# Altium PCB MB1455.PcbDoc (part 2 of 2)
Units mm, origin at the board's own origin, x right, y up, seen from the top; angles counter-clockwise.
Board outline 18.54 x 50.29 mm, 4 copper layers (Top Layer, Inner 1, Inner 2, Bottom Layer), stack 1.577 mm thick; 92 components, 84 nets, 350 pads, 195 vias.
Unrouted connection lines stored in the file: 7.
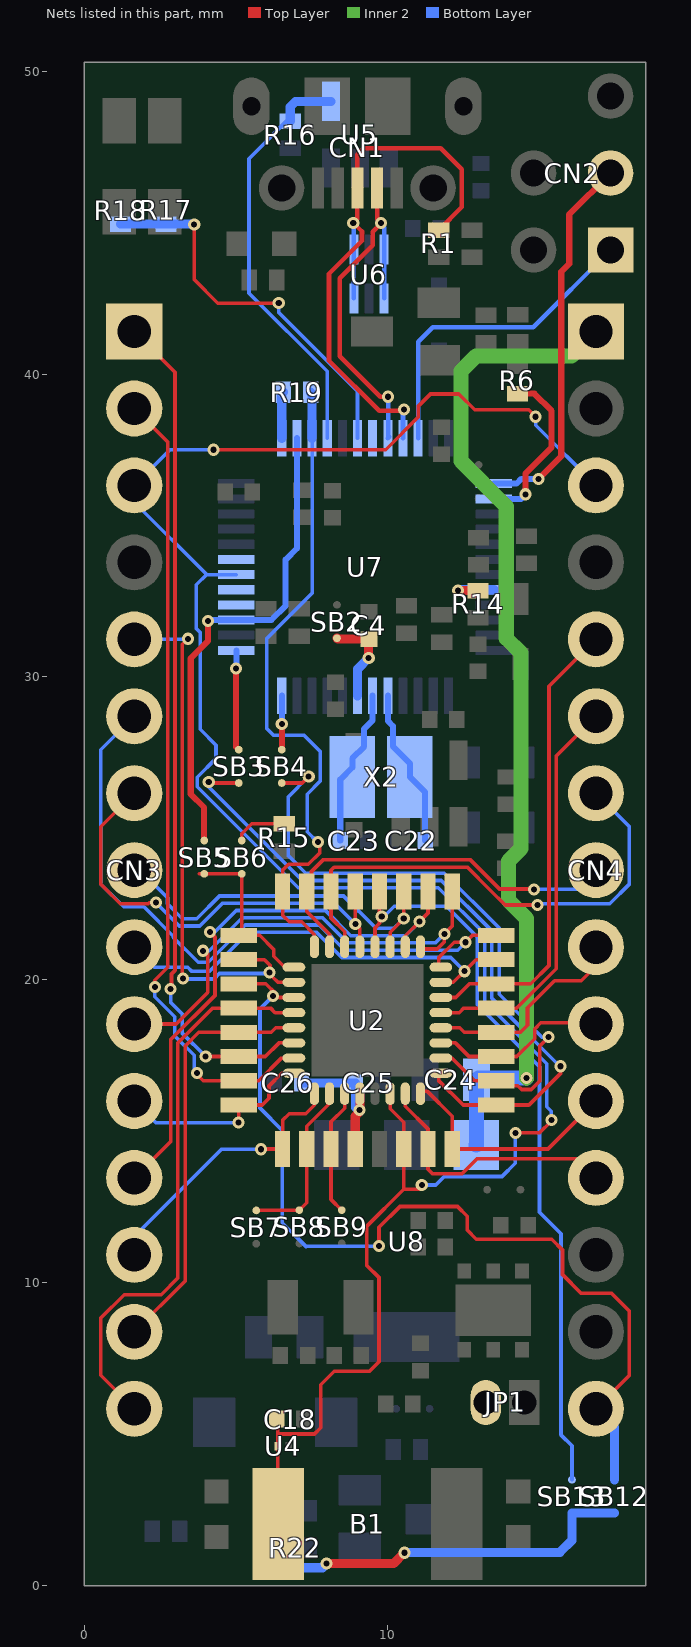
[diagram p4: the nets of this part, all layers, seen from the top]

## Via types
v1: diameter 0.4, hole 0.2, Top Layer to Bottom Layer, 195 vias

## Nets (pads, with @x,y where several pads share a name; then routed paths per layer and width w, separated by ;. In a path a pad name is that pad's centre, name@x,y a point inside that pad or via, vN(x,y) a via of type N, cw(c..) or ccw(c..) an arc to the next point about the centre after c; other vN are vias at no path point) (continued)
NetR14_2: R14.2 U7.44 | length 1.9
  Top Layer w0.3: v1(12.34,32.86) 12.99,32.86 R14.2@13,32.85
  Bottom Layer w0.3: v1(12.34,32.86) 12.36,32.88 U7.44@13.521,32.88
NetR15_2: R15.2 SB6.1 | length 1.8
  Top Layer w0.12: SB6.1@5.2,24.6 5.2,24.82 5.53,25.15 R15.2@6.6,25.15
NetR22_1: R22.1 SB12.2 SB13.2 | length 12.8
  Top Layer w0.3: v1(8,0.729) 10.209,0.729 v1(10.57,1.09)
  Bottom Layer w0.3: R22.1@6.521,1.25 6.521,0.739 6.665,0.595 7.866,0.595 v1(8,0.729) ; v1(10.57,1.09) 10.58,1.1 15.7,1.1 16.1,1.5 SB13.2@16.1,2.4 SB12.2@17.5,2.4
NetSB3_1: SB3.1 U2.9 | length 23.2
  Top Layer w0.12: v1(4.11,26.53) 4.14,26.5 SB3.1@5.1,26.5 ; U2.9@11.697,16.93 11.697,16.919 11.697,16.679 12.507,15.869 U2.9@13.597,15.869 14.679,15.869 15.72,16.91 v1(15.72,17.15)
  Bottom Layer w0.12: v1(4.11,26.53) 4.11,26.37 7.2,23.28 11.789,23.28 13.457,21.611 13.457,19.388 15.696,17.15 v1(15.72,17.15)
NetSB3_2: SB3.2 U7.13 | length 3.3
  Top Layer w0.2: v1(5.01,30.28) 5.01,27.69 SB3.2@5.1,27.6
  Bottom Layer w0.2: v1(5.01,30.28) 5.021,30.291 U7.13@5.021,30.88
NetSB4_1: SB4.1 U2.10 | length 21.7
  Top Layer w0.12: SB4.1@6.521,26.5 7.2,26.5 7.41,26.71 v1(7.41,26.72) ; U2.10@11.697,17.419 12.133,17.419 12.883,16.669 U2.10@13.597,16.669 13.756,16.51 14.313,16.51 14.443,16.38 14.757,16.38 15.04,16.663 15.04,17.82 v1(15.33,18.11)
  Bottom Layer w0.12: v1(7.41,26.72) 6.73,26.04 6.73,24.105 7.315,23.52 11.888,23.52 13.697,21.711 13.697,19.522 15.109,18.11 v1(15.33,18.11)
NetSB4_2: SB4.2 U7.12 | length 1.8
  Top Layer w0.2: SB4.2@6.521,27.6 v1(6.521,28.45) v1@6.521,28.49
  Bottom Layer w0.2: v1(6.521,28.45) U7.12@6.521,29.38
NetSB5_2: SB5.2 SB6.2 U2.25 | length 5.9
  Top Layer w0.12: 3.8,23.5 SB6.2@5.2,23.5 5.2,21.572 U2.25@5.097,21.469 5.796,21.469 6.26,21.005 6.26,20.78 6.621,20.419 U2.25@6.997,20.419
NetSB7_2: SB7.2 SB8.2 U2.2 | length 5.7
  Top Layer w0.12: SB7.2@5.68,12.39 5.69,12.4 SB8.2@7.1,12.4 7.347,12.647 U2.2@7.347,14.419 7.347,15.167 8.09,15.91 U2.2@8.09,16.31
NetSB9_2: SB9.2 U2.3 | length 4.3
  Top Layer w0.12: SB9.2@8.5,12.4 8.147,12.753 U2.3@8.147,14.419 8.147,15.314 8.597,15.764 U2.3@8.597,16.319
OSC_IN: C22.2 U7.5 X2.1 | length 5.3
  Bottom Layer w0.2: U7.5@10.021,29.38 10.021,28.549 10.19,28.38 10.19,27.71 10.75,27.15 X2.1@10.75,26.7 11.25,26.2 C22.2@11.25,24.6
OSC_OUT: C23.2 U7.6 X2.2 | length 5.2
  Bottom Layer w0.2: C23.2@8.45,24.6 8.45,26.61 8.85,27.01 8.85,27.31 9.24,27.7 9.24,28.289 9.521,28.57 U7.6@9.521,29.38
PA0: CN4.12 U2.7 | length 9
  Top Layer w0.12: U2.7@10.597,16.319 10.597,15.831 11.347,15.081 U2.7@11.347,14.419 11.347,13.746 11.493,13.6 12.47,13.6 12.96,14.09 16.263,14.09 CN4.12@16.891,13.462
PA1: CN4.11 U2.8 | length 7.9
  Top Layer w0.12: U2.8@11.097,16.319 11.33,16.319 12.147,15.501 U2.8@12.147,14.419 15.308,14.419 CN4.11@16.891,16.002
PA4: CN4.10 U2.11 | length 6
  Top Layer w0.12: U2.11@11.697,17.919 12.252,17.919 12.702,17.469 U2.11@13.597,17.469 14.279,17.469 14.87,18.06 14.87,18.38 15.071,18.581 16.852,18.581 CN4.10@16.891,18.542
PA5: CN4.9 U2.12 | length 7.1
  Top Layer w0.12: U2.12@11.697,18.419 12.394,18.419 12.544,18.269 U2.12@13.597,18.269 14.4,18.269 14.63,18.499 14.63,19.079 15.526,19.975 16.405,19.975 16.891,20.461 CN4.9@16.891,21.082
PA6: CN4.6 U2.13 | length 13.4
  Top Layer w0.12: U2.13@11.697,18.919 12.375,18.919 12.525,19.069 U2.13@13.597,19.069 14.281,19.069 15.58,20.368 15.58,27.391 CN4.6@16.891,28.702
PA7: CN4.5 U2.14 | length 15.5
  Top Layer w0.12: U2.14@11.697,19.419 12.268,19.419 12.718,19.869 U2.14@13.597,19.869 14.737,19.869 15.34,20.472 15.34,29.691 CN4.5@16.891,31.242
PA8: CN3.12 U2.18 | length 19.3
  Top Layer w0.12: CN3.12@1.651,13.462 2.85,14.661 2.85,18.019 4.317,19.487 4.317,21.413 v1(4.15,21.58) ; U2.18@10.597,21.019 U2.18@10.597,21.094 10.597,21.455 v1(11.071,21.929) 11.347,22.205 U2.18@11.347,22.919
  Bottom Layer w0.12: v1(4.15,21.58) 4.308,21.58 5.018,22.29 7.967,22.29 8.797,21.46 10.602,21.46 v1(11.071,21.929)
PA9: CN3.8 U2.19 | length 12.8
  Top Layer w0.12: U2.19@10.097,21.019 U2.19@10.097,21.094 10.097,21.574 v1(10.547,22.024) U2.19@10.547,22.919
  Bottom Layer w0.12: CN3.8@1.651,23.622 CN3.8@1.835,23.622 ; CN3.8@2.008,23.622 CN3.8@1.835,23.622 ; v1@10.53,22.01 10.22,21.7 9.632,21.7 8.562,22.77 4.463,22.77 3.713,22.02 3.239,22.02 2.75,22.509 2.75,22.707 CN3.8@1.835,23.622
PA10: CN3.7 U2.21 | length 15.1
  Top Layer w0.12: CN3.7@1.651,26.162 0.546,25.057 0.546,23.164 1.193,22.517 2.109,22.517 2.142,22.55 v1(2.37,22.55) v1@2.43,22.55 ; U2.21@8.947,22.919 v1(8.947,21.847) 9.097,21.697 U2.21@9.097,21.094 U2.21@9.097,21.019
  Bottom Layer w0.12: v1(2.37,22.55) 3.14,21.78 3.813,21.78 4.563,22.53 8.264,22.53 v1(8.947,21.847)
PA11: CN4.7 U2.22 | length 17
  Top Layer w0.12: U2.22@8.597,21.019 8.597,21.59 8.147,22.04 U2.22@8.147,22.919 8.147,23.62 8.247,23.72 12.65,23.72 13.391,22.98 ; 13.391,22.979 13.9,22.47 v1(14.96,22.47)
  Bottom Layer w0.12: v1(14.96,22.47) 14.96,22.5 14.977,22.517 17.349,22.517 17.996,23.164 17.996,25.057 CN4.7@16.891,26.162
PA12: CN4.8 U2.23 | length 13.1
  Top Layer w0.12: U2.23@8.097,21.019 8.097,21.507 7.347,22.257 U2.23@7.347,22.919 7.5,23.072 7.5,23.58 7.88,23.96 12.75,23.96 13.71,23 14.84,23 v1(14.85,22.99)
  Bottom Layer w0.12: v1(14.85,22.99) 16.259,22.99 CN4.8@16.891,23.622
PA15: CN3.5 U2.26 | length 18.4
  Top Layer w0.12: v1(3.26,20.04) 3.236,20.064 3.236,31.076 v1(3.42,31.26) ; U2.26@5.097,20.669 5.947,20.669 6.13,20.486 6.13,20.27 v1(6.11,20.25) ; v1@6.21,20.27 6.21,20.104 6.395,19.919 U2.26@6.997,19.919
  Bottom Layer w0.12: CN3.5@1.651,31.242 3.402,31.242 v1(3.42,31.26) ; v1(3.26,20.04) 3.27,20.03 4.28,20.03 4.46,20.21 6.07,20.21 v1(6.11,20.25)
PB0: CN3.9 U2.15 | length 14.5
  Top Layer w0.12: U2.15@11.697,19.919 12.185,19.919 v1(12.553,20.287) 12.935,20.669 U2.15@13.597,20.669
  Bottom Layer w0.12: CN3.9@1.651,21.082 2.313,20.42 3.417,20.42 3.557,20.28 4.129,20.28 5.419,21.57 7.669,21.57 8.499,20.74 12.1,20.74 v1(12.553,20.287)
PB1: CN3.6 U2.16 | length 22.6
  Top Layer w0.12: U2.16@11.697,20.419 11.697,20.728 12.211,21.242 v1(12.588,21.242) 12.815,21.469 U2.16@13.597,21.469
  Bottom Layer w0.12: CN3.6@1.651,28.702 0.546,27.597 0.546,23.164 1.3,22.41 1.97,22.41 2.94,21.44 2.94,21.403 3.763,20.58 4.089,20.58 5.319,21.81 7.768,21.81 8.598,20.98 12.326,20.98 v1(12.588,21.242)
PB2: CN3.10 U2.17 | length 15.9
  Top Layer w0.12: CN3.10@1.651,18.542 3.033,18.542 4.077,19.586 4.077,20.863 3.98,20.96 v1(3.92,20.96) ; U2.17@11.097,21.019 11.649,21.019 11.89,21.26 v1(11.89,21.52) 12.147,21.777 U2.17@12.147,22.919
  Bottom Layer w0.12: v1(3.92,20.96) 4.13,20.96 5.22,22.05 7.868,22.05 8.698,21.22 11.59,21.22 v1(11.89,21.52)
PB3: CN4.15 SB12.1 U2.27 | length 31.2
  Top Layer w0.12: U2.27@5.097,19.869 5.992,19.869 6.311,19.55 v1(6.23,19.47) ; 6.442,19.419 U2.27@6.922,19.419 U2.27@6.997,19.419 ; v1(9.73,11.21) 9.73,11.83 10.42,12.52 12.32,12.52 12.64,12.2 12.64,11.743 12.943,11.44 15.43,11.44 15.786,11.084 15.786,10.274 16.41,9.65 17.41,9.65 17.996,9.064 17.996,6.947 CN4.15@16.891,5.842
  Bottom Layer w0.12: v1@6.2,19.5 v1(6.23,19.47) 5.8,19.04 5.8,15.769 6.54,15.029 6.54,11.98 7.32,11.2 7.33,11.21 v1(9.73,11.21)
  Bottom Layer w0.3: CN4.15@16.891,5.842 17.5,5.233 SB12.1@17.5,3.5
PB4: CN3.15 U2.28 | length 18.8
  Top Layer w0.12: CN3.15@1.651,5.842 0.546,6.947 0.546,8.84 1.316,9.61 2.54,9.61 3.09,10.16 3.09,17.92 4.239,19.069 U2.28@5.097,19.069 6.15,19.069 6.3,18.919 U2.28@6.997,18.919
PB5: CN3.14 U2.29 | length 14
  Top Layer w0.12: CN3.14@1.651,8.382 3.33,10.061 3.33,17.821 3.778,18.269 U2.29@5.097,18.269 6.169,18.269 6.319,18.419 U2.29@6.997,18.419
PB6: CN3.1 U2.30 | length 28.2
  Top Layer w0.12: CN3.1@1.651,41.402 2.996,40.057 2.996,20.313 2.88,20.197 2.88,19.73 v1(2.85,19.7) ; v1(4.01,17.469) U2.30@5.097,17.469 5.976,17.469 6.426,17.919 U2.30@6.997,17.919
  Bottom Layer w0.12: v1(2.85,19.7) 2.85,19.259 3.23,18.879 3.23,18.249 v1(4.01,17.469)
PB7: CN3.2 U2.31 | length 26.9
  Top Layer w0.12: CN3.2@1.651,38.862 2.756,37.757 2.756,20.413 2.33,19.987 v1(2.33,19.76) ; v1(3.72,16.93) 3.72,16.88 3.931,16.669 U2.31@5.097,16.669 5.759,16.669 6.509,17.419 U2.31@6.997,17.419
  Bottom Layer w0.12: v1(2.33,19.76) 2.33,19.44 2.99,18.78 2.99,18.15 3.63,17.51 3.63,17.02 v1(3.72,16.93)
PB8: CN3.11 U2.32 | length 6.9
  Top Layer w0.12: v1(5.097,15.287) U2.32@5.097,15.869 5.879,15.869 6.1,16.09 6.1,16.5 6.519,16.919 U2.32@6.997,16.919
  Bottom Layer w0.12: CN3.11@1.651,16.002 2.366,15.287 v1(5.097,15.287)
PB9: CN3.13 U2.1 | length 9.4
  Top Layer w0.12: v1(5.831,14.41) 5.84,14.419 U2.1@6.547,14.419 6.547,15.363 6.766,15.582 7.316,15.582 7.597,15.863 U2.1@7.597,16.319
  Bottom Layer w0.12: CN3.13@1.651,10.922 1.651,11.531 4.53,14.41 v1(5.831,14.41)
PC6: SB13.1 U2.20 | length 25.1
  Top Layer w0.12: U2.20@9.597,21.019 9.597,21.716 9.747,21.866 v1@9.747,22.03 ; U2.20@9.747,22.919 v1@9.747,22.03 ; v1(9.82,22.09) 9.76,22.03 v1@9.747,22.03
  Bottom Layer w0.12: v1(9.82,22.09) 9.82,22.02 10.23,22.43 11.96,22.43 12.977,21.413 12.977,19.189 15.03,17.137 15.03,12.33 15.74,11.62 15.74,4.98 16.1,4.62 SB13.1@16.1,3.5
PWR_ENn: R16.1 U5.4 U7.28 | length 14.1
  Bottom Layer w0.12: R16.1@6.8,48.35 6.68,48.35 5.44,47.11 5.44,42.67 8.021,40.089 U7.28@8.021,37.88
  Bottom Layer w0.3: R16.1@6.8,48.35 6.8,48.82 6.98,49 U5.4@8.15,49
STLK_LED: R17.1 R18.1 U7.30 | length 12.9
  Top Layer w0.12: v1(3.63,44.94) 3.63,43.12 4.41,42.34 v1(6.42,42.34)
  Bottom Layer w0.12: v1(6.42,42.34) 6.42,42.029 9.021,39.428 U7.30@9.021,37.88
  Bottom Layer w0.3: R18.1@1.2,44.95 R17.1@2.7,44.95 3.62,44.95 v1(3.63,44.94)
STLK_RST: C4.2 SB2.2 U7.7 | length 3.1
  Top Layer w0.3: SB2.2@8.343,31.28 8.372,31.25 C4.2@9.4,31.25 9.39,31.24 v1(9.39,30.63)
  Bottom Layer w0.3: U7.7@9.021,29.38 9.021,30.261 v1(9.39,30.63)
STLK_SWCLK: CN2.3 U7.37 | length 12.6
  Top Layer w0.2: v1(15,36.54) 15.746,37.286 15.746,43.376 16.01,43.64 16.01,45.271 CN2.3@17.374,46.634
  Bottom Layer w0.2: U7.37@13.521,36.38 14.27,36.38 14.43,36.54 v1(15,36.54)
STLK_SWDIO: CN2.1 U7.34 | length 10.8
  Bottom Layer w0.15: U7.34@11.021,37.88 11.021,41.061 11.5,41.54 14.819,41.54 CN2.1@17.374,44.094
STLK_USB_D_N: CN1.2 U6.1 U6.6 U7.32 | length 12
  Top Layer w0.152: CN1.2@9.667,46.142 9.667,45.103 v1@9.75,45.02 ; v1@9.78,44.953 9.52,44.692 9.52,44.254 8.432,43.167 8.432,40.586 9.768,39.25 v1(10.03,39.25)
  Bottom Layer w0.152: U6.1@9.9,42.495 U6.6@9.9,44.105 v1@9.9,44.85 ; U7.32@10.021,37.88 10.07,37.929 10.03,37.969 v1(10.03,39.25)
  other v1: 9.8,44.99
STLK_USB_D_P: CN1.3 R1.1 U6.3 U6.4 U7.33 | length 20.2
  Top Layer w0.152: v1(8.88,44.99) v1@8.904,44.99 ; v1@8.92,44.953 9.168,44.705 9.168,44.4 8.08,43.312 8.08,40.44 9.732,38.788 10.495,38.788 v1@10.547,38.84 ; v1@8.92,44.99 v1@8.904,44.99 ; v1@10.547,38.83 v1(10.55,38.83) ; R1.1@11.7,44.75 12.464,45.514 12.464,46.755 11.763,47.456 9.23,47.456 9.017,47.243 CN1.3@9.017,46.142 9.017,45.103 v1@8.904,44.99
  Bottom Layer w0.152: v1(8.88,44.99) 8.89,44.99 8.9,44.98 U6.4@8.9,44.105 U6.3@8.9,42.495 ; U7.33@10.521,37.88 10.521,38.83 v1(10.55,38.83)
T_JRST: U7.19
T_JTCK: SB5.1 U7.15 U7.26 | length 16.1
  Top Layer w0.2: SB5.1@3.96,24.6 3.96,25.69 3.516,26.134 3.516,30.616 4.08,31.18 v1(4.08,31.85)
  Bottom Layer w0.2: v1(4.08,31.85) 4.11,31.88 U7.15@5.021,31.88 6.18,31.88 6.65,32.35 6.65,33.87 7.021,34.241 U7.26@7.021,37.88
T_JTDI: U7.17
T_JTDO: U7.16
T_JTMS: R19.2 U2.24 U7.27 | length 22.3
  Top Layer w0.12: U2.24@7.597,21.019 7.597,21.497 7.178,21.916 6.768,21.916 6.547,22.137 U2.24@6.547,22.919 6.547,23.617 6.745,23.815 7.396,23.815 7.77,24.189 7.77,24.52 7.74,24.55 v1(7.72,24.55)
  Bottom Layer w0.12: U7.27@7.521,37.88 7.521,32.761 6.02,31.26 6.02,28.31 6.26,28.07 7.259,28.07 7.79,27.539 7.79,26.563 7.36,26.133 7.36,24.89 7.7,24.55 v1(7.72,24.55)
  Bottom Layer w0.3: R19.2@7.471,39.4 7.521,39.35 U7.27@7.521,37.88
T_NRST: B1.1 C18.2 CN3.3 CN4.3 U2.6 U4.1 U7.18 | length 74.2
  Top Layer w0.12: v1(4.27,37.5) 9.95,37.5 11.02,38.57 11.02,38.93 11.43,39.34 12.367,39.34 12.887,38.82 14.67,38.82 v1(14.9,38.59) ; 6.388,5.01 7.6,5.01 7.81,5.22 7.81,6.64 8.25,7.08 9.42,7.08 9.73,7.39 9.73,10.175 9.32,10.585 9.32,11.863 10.547,13.09 ; U2.6@10.097,16.319 U2.6@10.097,16.244 10.097,15.748 10.547,15.298 U2.6@10.547,14.419 10.547,13.09 ; v1(11.143,13.229) 11.143,13.153 11.08,13.09 10.547,13.09 ; v1(14.23,14.95) 15.032,14.95 15.42,15.338 v1(15.42,15.37)
  Top Layer w0.127: B1.1@6.388,2.042 6.388,5.01 C18.2@6.388,5.462
  Top Layer w0.3: C18.2@6.35,5.5 C18.2@6.388,5.462 ; B1.1@6.388,2.042 B1.1@6.397,2.032
  Bottom Layer w0.12: v1(4.27,37.5) 2.829,37.5 CN3.3@1.651,36.322 1.651,35.769 4.04,33.38 ; U7.18@5.021,33.38 4.04,33.38 ; v1(11.143,13.229) 11.599,13.229 11.88,13.51 13.79,13.51 14.23,13.95 v1(14.23,14.95) ; v1(14.9,38.59) 14.9,38.313 CN4.3@16.891,36.322 ; v1(15.42,15.37) 15.42,15.66 15.27,15.81 15.27,17.236 13.217,19.289 13.217,21.512 11.689,23.04 7.063,23.04 3.73,26.373 3.73,26.687 4.35,27.307 4.35,27.75 3.83,28.27 3.83,31.47 3.7,31.6 3.7,33.039 4.04,33.38
T_SWDIO_IN: R19.1 U7.25 | length 1.5
  Bottom Layer w0.3: U7.25@6.521,37.88 6.521,39.35 R19.1@6.571,39.4
T_SWO: U7.31
USB_RENUMn: R6.2 U7.38 | length 5.6
  Top Layer w0.2: R6.2@14.3,39.35 14.86,39.35 15.426,38.784 15.426,37.576 14.57,36.72 v1(14.57,36.03)
  Bottom Layer w0.2: U7.38@13.521,35.88 14.42,35.88 v1(14.57,36.03)
VDD: C25.2 C26.2 JP1.2 U2.4 | length 4.7
  Top Layer w0.3: U2.4@8.947,14.419 8.947,15.499 9.097,15.649 U2.4@9.097,16.319
  Bottom Layer w0.3: C26.2@7.172,16.6 C25.2@8.95,16.6 8.95,15.79 9.04,15.7 v1(9.09,15.7)
VIN: C24.2 CN4.1 U8.3 | length 33.4
  Inner 2 w0.5: v1(14.6,16.76) 14.6,22.024 14,22.624 14,23.92 14.42,24.34 14.42,30.79 13.93,31.28 13.93,35.63 12.434,37.126 12.434,40.1 12.934,40.6 16.089,40.6 CN4.1@16.891,41.402
  Bottom Layer w0.5: U8.3@12.943,14.554 12.95,14.562 C24.2@12.95,16.7 13.01,16.76 v1(14.6,16.76)
pads on no net: CN2.5 U3.3 U3.5 U7.4 U7.11 U7.14 U7.21 U7.22 U7.40 U7.41 U7.42 U7.43 U7.45 U7.46

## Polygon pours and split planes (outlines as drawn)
3V3 on Inner 2 "3V3_L03_P010" (solid, remove dead copper, pour order 10): 4.945,22.875 4.945,20.145 3.79,18.99 3.79,7.12 4.39,6.52 5.1,6.52 5.19,6.43 5.17,6.41 5.17,4.63 4.35,3.81 1.73,3.81 1.39,3.47 1.39,2.15 1.91,1.63 7.15,1.63 8.9,3.38 8.9,6.35 11.35,6.35 11.35,4.72 12.14,3.93 13.599,3.93 14.03,4.361 13.85,4.541 13.85,8.96 11.72,11.09 11.72,13.115 11.745,13.115 11.94,13.31 19.55,13.31 19.65,13.21 19.65,-0.37 18.87,-1.15 -0.59,-1.15 -1.64,-0.1 -1.64,34.12 -0.81,34.95 6.357,34.95 7.33,33.977 7.33,25.259
E5V on Inner 2 "E5V_L03_P004" (solid, remove dead copper, pour order 4): 5.105,22.855 5.105,20.084 3.87,18.85 3.87,7.04 4.29,6.62 5.19,6.62 5.63,7.06 5.63,17.07 7.717,19.157 7.717,19.16 14.31,19.16 14.307,28.527 13.86,28.975 13.655,29.18 13.13,29.18 13.035,29.085 9.31,25.36 7.61,25.36
3V3_STLK on Inner 2 "3V3_STLK_L03_P000" (solid, remove dead copper, pour order 0): 12.17,36.857 12.17,40.35 12.76,40.94 19.06,40.94 19.46,41.34 19.36,41.44 19.36,51.15 19.03,51.48 0.635,51.48 0.265,51.11 0.285,51.09 0.285,35.09 6.335,35.09 7.405,34.02 7.405,25.73 7.735,25.4 9.135,25.4 13.865,30.13 13.865,35.178
VDD on Inner 2 "VDD_L03_P002" (solid, remove dead copper, pour order 2): 8.93,10.39 8.93,6.56 9.04,6.45 11.39,6.45 11.46,6.38 11.46,4.9 12.3,4.06 13.56,4.06 13.8,4.3 13.8,8.83 11.72,10.91 11.72,15.32 10.77,16.27 8.75,16.27 8.33,15.85 8.33,10.99
5V on Inner 2 "5V_L03_P008" (solid, remove dead copper, pour order 8): 18.78,13.44 11.8,13.44 11.8,15.422 10.82,16.41 8.69,16.41 8.2,15.92 8.2,10.94 8.78,10.36 8.78,3.44 7.1,1.76 1.97,1.76 1.52,2.21 1.52,3.39 1.81,3.68 4.37,3.68 5.19,4.5 5.19,6.43 5.76,7 5.768,16.89 5.768,16.988 7.81,19.03 11.8,19.03 14.84,19.03 14.84,30.91 14.26,31.49 14.26,35.8 12.77,37.29 12.77,39.9 13.08,40.21 19,40.21 19.15,40.06 19.15,15.19 19.15,13.81
GND on Inner 1 "GND_L02_P012" (solid, remove dead copper, pour order 12): -1.95,53.4 20.79,53.4 23.21,50.98 23.21,0.57 18.9,-3.74 -1.06,-3.74 -6.98,2.18 -6.98,51.84 -5.55,53.27
GND on Bottom Layer "GND_L04_P014" (solid, remove dead copper, pour order 14): -3.62,54.23 22.32,54.23 23.93,52.62 23.93,-1.1 20.54,-4.49 -3.9,-4.49 -5.35,-3.04 -5.35,51.45
GND on Top Layer "GND_L01_P016" (solid, remove dead copper, pour order 16): -2.23,54.12 19.2,54.12 22.43,50.89 22.43,1.97 17.41,-3.05 -6.57,-3.05 -6.57,51.73 -4.96,53.34

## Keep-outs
Keep-Out Layer:
  the board outline again, w0.1

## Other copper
Top Layer:
  text ".Layer_Name" at -22.785,-18.354 h3
  text ".GTL" at 18.91,-18.354 h3
Inner 1:
  text ".Layer_Name" at -22.785,-18.354 h3
  text ".G1" at 18.91,-18.354 h3
Inner 2:
  text ".Layer_Name" at -22.785,-18.354 h3
  text ".G2" at 18.91,-18.354 h3
Bottom Layer:
  text ".GBL" at 7.706,-18.386 h3
  text ".Layer_Name" at 49.02,-18.386 h3

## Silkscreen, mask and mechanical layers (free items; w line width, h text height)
Top Overlay:
  circle w0.203: c0.3,41.387 r0.072
  circle w0.203: c18.2,41.451 r0.072
  text "STLK" at 13.45,48.9 h1.02
  text "CN3" at 0.8,42.6 h1.02
  text "CN4" at 15.995,42.5 h1.02
  text "D1" at 2.8,42.4 h1.02 r270
  text "VIN" at 15.1,42.086 h1.02 r270
  text "GND" at 15.159,39.889 h1.02 r270
  text "D0" at 2.8,39.381 h1.02 r270
  text "MB1455D" at 4.1,37.9 h0.91
  text "RST" at 2.8,37.18 h1.02 r270
  text "RST" at 15.1,37.075 h1.02 r270
  text "GND" at 2.8,34.6 h1.02 r270
  text "5V" at 15.209,34.3 h1.02 r270
  text "A7" at 15.225,31.9 h1.02 r270
  text "D2" at 2.8,31.7 h1.02 r270
  text "D3" at 2.8,29.3 h1.02 r270
  text "A6" at 15.159,29.3 h1.02 r270
  text "A5" at 15.159,26.725 h1.02 r270
  text "D4" at 2.8,26.7 h1.02 r270
  text "D5" at 2.4,25.319 h1.02 r270
  text "A4" at 15.159,24.3 h1.02 r270
  text "D6" at 2.8,21.6 h1.02 r270
  text "A3" at 15.159,21.6 h1.02 r270
  text "A2" at 15.2,19.1 h1.02 r270
  text "D7" at 2.8,19 h1.02 r270
  text "A1" at 15.209,16.6 h1.02 r270
  text "D8" at 2.8,16.5 h1.02 r270
  text "A0" at 15.24,14.79 h1.02 r270
  text "D9" at 2.8,13.9 h1.02 r270
  text "D10" at 2.8,11.8 h1.02 r270
  text "REF" at 15.21,11.71 h1.02 r270
  text "3V3" at 15.209,9.2 h1.02 r270
  text "D11" at 2.8,9.1 h1.02 r270
  text "D13" at 15.2,6.6 h1.02 r270
  text "D12" at 2.8,6.5 h1.02 r270
  text ".Layer_Name" at -22.785,-18.354 h3
  text ".GTO" at 18.91,-18.354 h3
Bottom Overlay:
  lines w0.1: 9,18 15,18 15,23 9,23 9,18
  text "IDD" at 14.63,8.01 h1.02
  text ".GBO" at 7.706,-18.386 h3
  text ".Layer_Name" at 49.02,-18.386 h3
Top Paste:
  text ".Layer_Name" at -22.785,-18.354 h3
  text ".GTP" at 18.91,-18.354 h3
Bottom Paste:
  text ".GBP" at 7.706,-18.386 h3
  text ".Layer_Name" at 49.02,-18.386 h3
Top Solder:
  text ".Layer_Name" at -22.785,-18.354 h3
  text ".GTS" at 18.91,-18.354 h3
Bottom Solder:
  text ".GBS" at 7.706,-18.386 h3
  text ".Layer_Name" at 49.02,-18.386 h3
M1-Board Shape:
  the board outline again, w0.1
M2-Board Dimensions:
  text ".Layer_Name" at -22.785,-18.354 h3
  text ".GM2" at 18.91,-18.354 h3
M14-Top Assembly:
  text ".Layer_Name" at -22.785,-18.354 h3
  text ".GM14" at 18.91,-18.354 h3
M15-Bottom Assembly:
  text ".GM15" at 7.706,-18.386 h3
  text ".Layer_Name" at 49.02,-18.386 h3
Drill Drawing:
  drawing of 477 lines, arcs and shapes, not listed
  text "PCB SPECIFICATIONS :" at -5.928,99.978 h3
  text "PCB : TYPE 3" at 141.563,99.806 h3
  text "A.   MATERIAL :" at -5.928,95.978 h3
  text "FR-4" at 32.571,95.978 h3
  text "TG-170" at 49.071,95.978 h3
  text "X  TG-150" at 67.321,95.978 h3
  text "TG-140" at 83.321,95.978 h3
  text "ASPECT-RATIO, AXE Z :" at 141.563,94.306 h3
  text "B.   MATERIAL FAMILY :" at -5.928,92.978 h3
  text "N/A" at 32.571,92.978 h3
  text "C.   SOLDERMASK COLOR :" at -5.928,89.978 h3
  text "GREEN" at 32.571,89.978 h3
  text "X  WHITE" at 49.071,89.978 h3
  text "RED" at 67.321,89.978 h3
  text "BLACK" at 83.321,89.978 h3
  text "6:1 to 8:1 / LEVEL \"B\"" at 141.582,87.559 h3
  text "D.   SILKSCREEN COLOR :" at -5.928,86.978 h3
  text "WHITE" at 32.571,86.978 h3
  text "YELLOW" at 49.071,86.978 h3
  text "BLACK" at 67.321,86.978 h3
  text "X  Blue ink PANTONE 2955" at 83.321,86.978 h3
  text "E.   SURFACE FINISH :" at -5.928,83.978 h3
  text "X  ENIG" at 32.571,83.978 h3
  text "IMMERSION SILVER" at 49.071,83.978 h3
  text "IMMERSION TIN" at 83.321,83.978 h3
  text "MINIMUM PARAMETERS" at 141.609,81.958 h3
  text "HASL" at 32.571,80.978 h3
  text "HASL (PB-FREE)" at 49.071,80.978 h3
  text "GOLDEN FINGER" at 83.321,80.978 h3
  text "F.   IMPEDANCE CONTROL :" at -5.928,77.978 h3
  text "NO" at 32.571,77.978 h3
  text "X  YES  (SEE IMPEDANCE TABLE FOR DETAIL INFORMATION)" at 49.071,77.978 h3
  text "DEFAULT" at 141.609,76.458 h3
  text "G.   THROUGH VIA :" at -5.928,74.978 h3
  text "PLUG THE VIAS WHICH ARE COVERED WITH SOLDERMASK ONE OR TWO SIDE." at 32.571,74.978 h3
  text "PLUG MATERIAL :" at 32.571,71.978 h3
  text "X  SOLDERMASK" at 58.071,71.978 h3
  text "NON-CONDUCTIVE EPOXY." at 83.321,71.978 h3
  text "TRACKS : 0.127mm           / GAPS : 0.127mm" at 141.609,70.708 h3
  text "H.   STACK-UP :" at -5.928,68.978 h3
  text "SEE LAYER STACK-UP SEQUENCE FOR OVERALL THICKNESS." at 32.571,68.978 h3
  text "Layer" at 24.399,62.694 h1.52
  text "Name" at 34.81,62.694 h1.52
  text "Material" at 58.426,62.694 h1.52
  text "Thickness" at 80.264,62.694 h1.52
  text "Constant" at 96.77,62.694 h1.52
  text "Board Layer Stack" at 111.244,62.694 h1.52
  text "IMPEDANCE TABLE   USB FS STLINK" at 141.17,61.924 h3
  text "Top Overlay" at 34.81,59.646 h1.52
  text "LAYER" at 145.42,56.924 h3
  text "TRACE" at 161.67,56.924 h3
  text "SPACING" at 172.17,56.924 h3
  text "IMPEDANCE" at 185.67,56.924 h3
  text "IMPEDANCE" at 202.67,56.924 h3
  text "TOL." at 221.42,56.924 h3
  text "Top Solder" at 34.81,56.598 h1.52
  text "Solder Resist" at 58.426,56.598 h1.52
  text "0.015mm" at 80.264,56.598 h1.52
  text "3.5" at 96.77,56.598 h1.52
  text "(mm)" at 175.495,54.449 h2.5
  text "(mm)" at 163.67,54.399 h2.5
  text "(Single ended)" at 186.17,54.174 h2.5
  text "(Differential)" at 203.92,54.174 h2.5
  text "1" at 24.399,53.55 h1.52
  text "Top Layer" at 34.81,53.55 h1.52
  text "0.035mm" at 80.264,53.55 h1.52
  text "+/- 15%" at 220.475,50.534 h3
  text "Dielectric 1" at 34.81,50.502 h1.52
  text "FR-4" at 58.426,50.502 h1.52
  text "0.254mm" at 80.264,50.502 h1.52
  text "4.2" at 96.77,50.502 h1.52
  text "0.155" at 162.645,50.449 h3
  text "TOP" at 141.65,50.409 h3
  text "0.226" at 174.67,50.424 h3
  text "n/a" at 189.025,50.359 h3
  text "90 ohm" at 205.111,50.183 h3
  text "2" at 24.399,47.454 h1.52
  text "Inner 1" at 34.81,47.454 h1.52
  text "0.036mm" at 80.264,47.454 h1.52
  text "+/- 15%" at 220.48,47.019 h3
  text "0.130" at 162.65,46.934 h3
  text "0.251" at 174.675,46.909 h3
  text "LAYER 1" at 143.595,46.874 h3
  text "90 ohm" at 205.111,46.881 h3
  text "n/a" at 189.03,46.844 h3
  text "Dielectric 3" at 34.81,44.406 h1.52
  text "0.927mm" at 80.264,44.406 h1.52
  text "4.2" at 96.77,44.406 h1.52
  text "3" at 24.399,41.358 h1.52
  text "Inner 2" at 34.81,41.358 h1.52
  text "0.036mm" at 80.264,41.358 h1.52
  text "Dielectric 2" at 34.81,38.31 h1.52
  text "0.254mm" at 80.264,38.31 h1.52
  text "4.2" at 96.77,38.31 h1.52
  text "4" at 24.399,35.262 h1.52
  text "Bottom Layer" at 34.81,35.262 h1.52
  text "0.035mm" at 80.264,35.262 h1.52
  text "Bottom Solder" at 34.81,32.214 h1.52
  text "Solder Resist" at 58.426,32.214 h1.52
  text "0.015mm" at 80.264,32.214 h1.52
  text "3.5" at 96.77,32.214 h1.52
  text "Bottom Overlay" at 34.81,29.166 h1.52
  text "Symbol" at 24.819,23.764 h2.16
  text "Count" at 33.275,23.764 h2.16
  text "Hole Size" at 42.067,23.764 h2.16
  text "Plated" at 57.607,23.764 h2.16
  text "Hole Type" at 65.033,23.764 h2.16
  text "Drill Layer Pair" at 75.839,23.764 h2.16
  text "Via/Pad" at 96.328,23.764 h2.16
  text "Pad Shape" at 105.184,23.764 h2.16
  text "Template" at 116.754,23.764 h2.16
  text "Description" at 141.832,23.764 h2.16
  text "Hole Tolerance (+)" at 153.452,23.764 h2.16
  text "Hole Tolerance (-)" at 171.513,23.764 h2.16
  text "Hole Length" at 189.09,23.764 h2.16
  text "Routed Path Length" at 204.522,23.764 h2.16
  text "2" at 33.275,20.033 h1.8
  text "0.60mm (23.62mil)" at 42.067,20.033 h1.8
  text "PTH" at 57.607,20.033 h1.8
  text "Slot" at 65.033,20.033 h1.8
  text "Top Layer - Bottom Layer" at 75.839,20.033 h1.8
  text "Pad" at 96.328,20.033 h1.8
  text "Rounded" at 105.184,20.033 h1.8
  text "r190_120h60_130r60m200_130" at 116.754,20.033 h1.8
  text "1.30mm (51.18mil)" at 189.09,20.033 h1.8
  text "0.70mm (27.56mil)" at 204.522,20.033 h1.8
  text "2" at 33.275,16.303 h1.8
  text "0.80mm (31.50mil)" at 42.067,16.303 h1.8
  text "PTH" at 57.607,16.303 h1.8
  text "Round" at 65.033,16.303 h1.8
  text "Top Layer - Bottom Layer" at 75.839,16.303 h1.8
  text "Pad" at 96.328,16.303 h1.8
  text "(Mixed)" at 105.184,16.303 h1.8
  text "(Mixed)" at 116.754,16.303 h1.8
  text "-" at 189.09,16.303 h1.8
  text "-" at 204.522,16.303 h1.8
  text "7" at 33.275,12.573 h1.8
  text "0.90mm (35.43mil)" at 42.067,12.573 h1.8
  text "PTH" at 57.607,12.573 h1.8
  text "Round" at 65.033,12.573 h1.8
  text "Top Layer - Bottom Layer" at 75.839,12.573 h1.8
  text "Pad" at 96.328,12.573 h1.8
  text "(Mixed)" at 105.184,12.573 h1.8
  text "(Mixed)" at 116.754,12.573 h1.8
  text "-" at 189.09,12.573 h1.8
  text "-" at 204.522,12.573 h1.8
  text "30" at 33.275,8.843 h1.8
  text "1.10mm (43.31mil)" at 42.067,8.843 h1.8
  text "PTH" at 57.607,8.843 h1.8
  text "Round" at 65.033,8.843 h1.8
  text "Top Layer - Bottom Layer" at 75.839,8.843 h1.8
  text "Pad" at 96.328,8.843 h1.8
  text "Rounded" at 105.184,8.843 h1.8
  text "(Mixed)" at 116.754,8.843 h1.8
  text "-" at 189.09,8.843 h1.8
  text "-" at 204.522,8.843 h1.8
  text "195" at 33.275,5.112 h1.8
  text "0.20mm (7.87mil)" at 42.067,5.112 h1.8
  text "PTH" at 57.607,5.112 h1.8
  text "Round" at 65.033,5.112 h1.8
  text "Top Layer - Bottom Layer" at 75.839,5.112 h1.8
  text "Via" at 96.328,5.112 h1.8
  text "Rounded" at 105.184,5.112 h1.8
  text "v40h20" at 116.754,5.112 h1.8
  text "-" at 189.09,5.112 h1.8
  text "-" at 204.522,5.112 h1.8
  text "236 Total" at 33.275,1.382 h1.8
  text "Slot definitions :" at 24.819,-1.229 h1.8
  text "Routed Path Length" at 37.094,-1.229 h1.8
  text "= Calculated from tool start centre position to tool end centre position." at 52.307,-1.229 h1.8
  text "Hole Length" at 37.094,-2.721 h1.8
  text "= Routed Path Length + Tool Size = Slot length as defined in the PCB layout" at 46.659,-2.721 h1.8
  text ".Layer_Name" at -22.785,-18.354 h3
  text ".DRL" at 18.91,-18.354 h3
M20-Top Title Box:
  circle w0.254: c55.219,-25.074 r1.3
  region: 40.741,-26.167 29.985,-26.167 30.978,-23.675 38.836,-23.675 39.285,-22.915 41.493,-25.464
  region: 54.744,-17.838 39.217,-17.838 38.523,-19.613 37.312,-20.838 35.915,-18.978 35.915,-17.327 37.058,-15.93 38.494,-15.552 54.744,-15.552
  lines w0.254: 30.978,-23.675 39.77,-23.675 36.704,-20.137 cw(c38.508,-18.193) 38.748,-15.552 55.512,-15.552 54.75,-17.838 ; 34.292,-15.305 cw(c36.718,-16.275) 36.955,-13.673 ; 34.331,-15.272 29.985,-26.167 49.308,-26.167 ccw(c49.556,-23.433) 52.106,-24.453 ; 36.071,-19.207 41.493,-25.464 ; 36.325,-19.207 41.63,-25.328 ; 36.325,-18.953 41.63,-25.074 ; 36.423,-17.838 49.416,-17.838 ; 36.452,-18.826 41.757,-24.947 ; 36.579,-18.699 41.884,-24.82 ; 36.706,-18.572 42.011,-24.693 ; 36.833,-18.445 42.138,-24.566 ; 36.888,-16.493 42.193,-22.614 ; 36.956,-13.673 56.406,-13.673 52.106,-24.45 ; 36.96,-18.318 42.211,-24.376 ; 36.96,-18.064 42.265,-24.185 ; 36.96,-17.81 42.265,-23.931 ; 36.96,-16.921 42.265,-23.042 ; 37.087,-17.683 42.392,-23.804 ; 37.087,-17.302 42.392,-23.423 ; 38.459,-23.688 ccw(c38.564,-23.153) 38.861,-22.696 ; 39.545,-17.824 ccw(c39.519,-18.392) 39.189,-18.854 41.554,-21.583 cw(c39.75,-23.526) 40.483,-26.075 ; 45.827,-25.963 48.716,-17.584 ; 46.049,-25.913 48.918,-17.593 ; 46.176,-25.913 49.045,-17.593 ; 46.43,-25.913 49.299,-17.593 ; 46.684,-25.913 49.553,-17.593 ; 46.938,-25.913 49.807,-17.593 ; 47.192,-25.913 50.061,-17.593 ; 47.446,-25.913 50.315,-17.593 ; 47.7,-25.913 50.569,-17.593 ; 47.954,-25.913 50.823,-17.593 ; 48.162,-25.963 51.052,-17.584 ; 51.052,-17.838 54.744,-17.838 ; 54.076,-17.835 54.838,-15.549 ; 54.242,-17.838 55.004,-15.552 ; 54.496,-17.838 55.258,-15.552
  lines w0.3: -31.785,-25.054 28.215,-25.054 ; -31.785,-20.054 28.215,-20.054 ; -31.785,-15.054 28.215,-15.054 ; 8.215,-30.054 8.215,-15.054 ; 28.215,-30.054 28.215,-10.054 ; 45.827,-25.963 48.162,-25.963 ; -31.785,-30.054 58.215,-30.054 58.215,-10.054 -31.785,-10.054 -31.785,-30.054
  text "Project: '.Board_Name'" at -30.785,-13.27 h3
  text "Layer:" at -30.785,-18.354 h3
  text "Gerber:" at 9.204,-18.354 h3
  text "Variant: '.VariantName'" at -30.785,-23.354 h3
  text "Ref: '.Board_Reference'" at 9.331,-23.354 h3
  text "R" at 54.711,-25.836 h1.52
  text "Date: '.Board_Document_Date'" at -30.785,-28.354 h3
  text "Rev: '.Board_PCB_Revision'" at 9.274,-28.354 h3
M21-Bottom Title Box:
  circle w0.254: c-28.602,-25.074 r1.3
  region: -28.128,-17.838 -12.6,-17.838 -11.906,-19.613 -10.695,-20.838 -9.298,-18.978 -9.298,-17.327 -10.441,-15.93 -11.877,-15.552 -28.128,-15.552
  region: -14.124,-26.167 -3.368,-26.167 -4.362,-23.675 -12.219,-23.675 -12.668,-22.915 -14.877,-25.464
  lines w0.254: -28.641,-15.552 -27.879,-17.838 ; -28.387,-15.552 -27.625,-17.838 ; -28.221,-15.549 -27.459,-17.835 ; -28.133,-17.838 -28.895,-15.552 -12.131,-15.552 cw(c-11.891,-18.193) -10.088,-20.137 -13.154,-23.675 -4.362,-23.675 ; -28.128,-17.838 -24.435,-17.838 ; -25.489,-24.453 ccw(c-22.94,-23.433) -22.691,-26.167 -3.368,-26.167 -7.715,-15.272 ; -25.49,-24.45 -29.789,-13.673 -10.34,-13.673 ; -24.435,-17.584 -21.546,-25.963 ; -24.207,-17.593 -21.337,-25.913 ; -23.953,-17.593 -21.083,-25.913 ; -23.699,-17.593 -20.829,-25.913 ; -23.445,-17.593 -20.575,-25.913 ; -23.191,-17.593 -20.321,-25.913 ; -22.937,-17.593 -20.067,-25.913 ; -22.799,-17.838 -9.806,-17.838 ; -22.683,-17.593 -19.813,-25.913 ; -22.429,-17.593 -19.559,-25.913 ; -22.302,-17.593 -19.432,-25.913 ; -22.099,-17.584 -19.21,-25.963 ; -15.775,-23.804 -10.47,-17.683 ; -15.775,-23.423 -10.47,-17.302 ; -15.648,-24.185 -10.343,-18.064 ; -15.648,-23.931 -10.343,-17.81 ; -15.648,-23.042 -10.343,-16.921 ; -15.594,-24.376 -10.343,-18.318 ; -15.576,-22.614 -10.271,-16.493 ; -15.521,-24.566 -10.216,-18.445 ; -15.394,-24.693 -10.089,-18.572 ; -15.267,-24.82 -9.962,-18.699 ; -15.14,-24.947 -9.835,-18.826 ; -15.013,-25.328 -9.708,-19.207 ; -15.013,-25.074 -9.708,-18.953 ; -14.877,-25.464 -9.454,-19.207 ; -13.866,-26.075 cw(c-13.134,-23.526) -14.937,-21.583 -12.572,-18.854 ccw(c-12.903,-18.392) -12.929,-17.824 ; -12.245,-22.696 ccw(c-11.947,-23.153) -11.842,-23.688 ; -10.338,-13.673 cw(c-10.102,-16.275) -7.676,-15.305
  lines w0.3: -21.546,-25.963 -19.21,-25.963 ; -1.785,-30.054 -1.785,-10.054 ; -1.785,-25.054 58.215,-25.054 ; -1.785,-20.054 58.215,-20.054 ; -1.785,-15.054 58.215,-15.054 ; 18.215,-30.054 18.215,-15.054 ; -31.785,-30.054 -31.785,-10.054 58.215,-10.054 58.215,-30.054 -31.785,-30.054
  text "Project: '.Board_Name'" at 57.021,-13.27 h3
  text "Gerber:" at 17.032,-18.354 h3
  text "Layer:" at 57.02,-18.354 h3
  text "Ref: '.Board_Reference'" at 17.032,-23.354 h3
  text "Variant: '.VariantName'" at 57.021,-23.354 h3
  text "R" at -28.094,-25.836 h1.52
  text "Rev: '.Board_PCB_Revision'" at 17.089,-28.354 h3
  text "Date: '.Board_Document_Date'" at 57.021,-28.354 h3

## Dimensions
1.651,5.842 to 0,0 on M2-Board Dimensions
16.891,5.842 to 18.54,0 on M2-Board Dimensions
1.651,5.842 to 16.891,5.842 on M2-Board Dimensions
0,0 to 1.651,5.842 on M2-Board Dimensions
0,50.29 to 18.54,50.29 on M2-Board Dimensions
0,0 to 0.03,50.3 on M2-Board Dimensions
